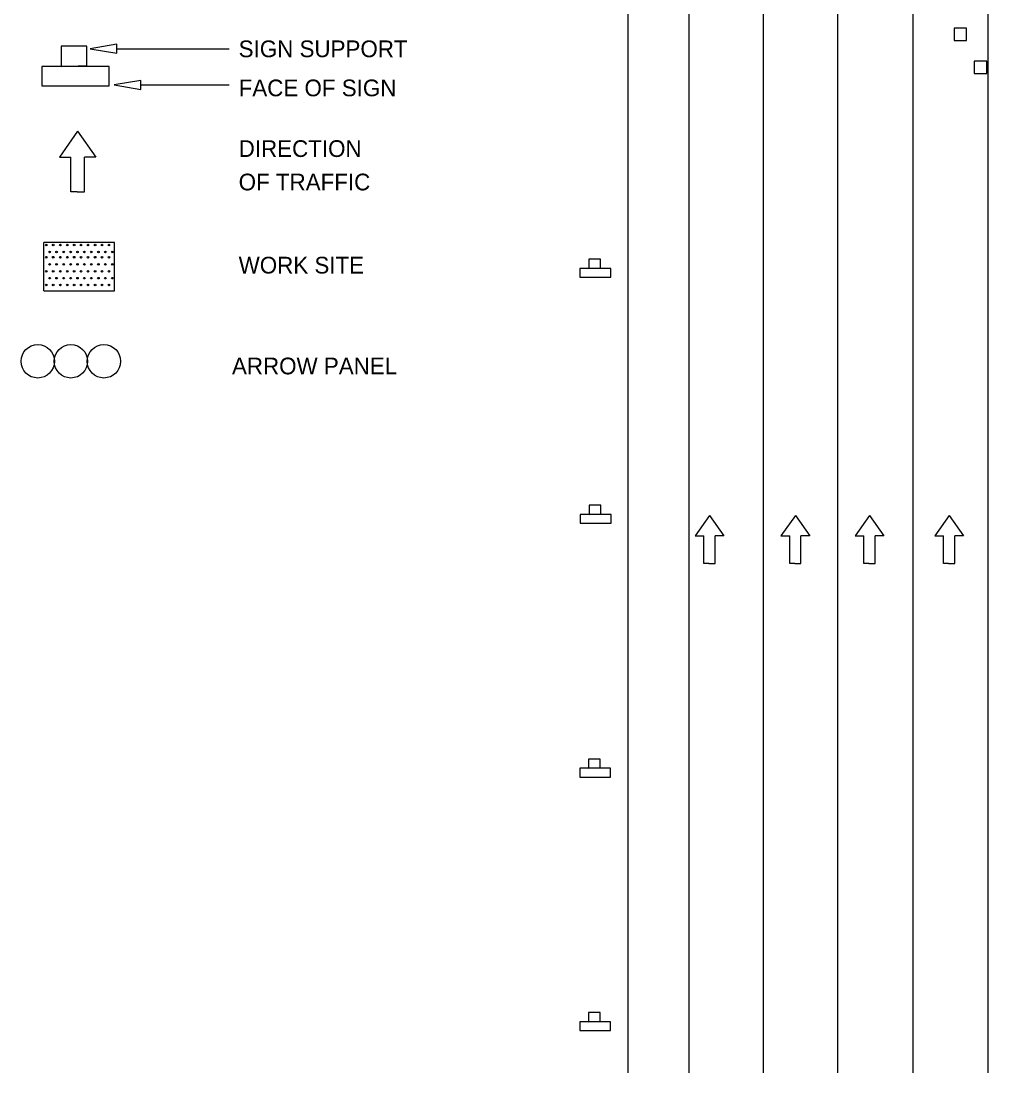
# Model space of a CAD drawing. Extents: x 1531.3 to 1538.6, y 1529.6 to 1539.7.
# Drawn here: x 1531.46 to 1534.931, y 1531.412 to 1535.19 of the extents above; entities that cross this region are included whole.
import ezdxf

# ---------------------------------------------------------------- set-up
doc = ezdxf.new("R2010")
doc.units = 0
for name, color, linetype in [('DETL-DIMS', 7, 'Continuous'), ('DETL-LINE', 7, 'Continuous'), ('DETL-NOTE', 7, 'Continuous'), ('USER-BORD', 7, 'Continuous')]:
    doc.layers.add(name, color=color, linetype=linetype)

# ---------------------------------------------------------------- blocks, each defined once
blk = doc.blocks.new('TD')
at = {"layer": 'USER-BORD'}
for p, q in [((0, 0), (-0.0054, -0.0077)), ((0, 0), (0.0054, -0.0077)), ((-0.0054, -0.0077), (-0.0021, -0.0077)), ((-0.0021, -0.018), (-0.0021, -0.0077)), ((0.0021, -0.018), (0.0021, -0.0077)), ((0.0054, -0.0077), (0.0021, -0.0077)), ((-0.0002, -0.018), (-0.0021, -0.018)), ((-0.0002, -0.018), (0.0002, -0.018)), ((0.0002, -0.018), (0.0021, -0.018))]:
    blk.add_line(p, q, dxfattribs=at)
blk = doc.blocks.new('PANEL0')
at = {"layer": 'USER-BORD'}
for centre in [(0.00309, -0.00012), (0.00928, -0.00012), (0.01546, -0.00012)]:
    blk.add_circle(centre, 0.00312, dxfattribs=at)
blk = doc.blocks.new('DIR4')
at = {"layer": 'USER-BORD'}
for p, q in [((0, 0.0001), (-0.0034, -0.0048)), ((0, 0.0001), (0.0034, -0.0048)), ((-0.0034, -0.0048), (-0.0013, -0.0048)), ((-0.0013, -0.0113), (-0.0013, -0.0048)), ((0.0034, -0.0048), (0.0013, -0.0048)), ((0.0013, -0.0113), (0.0013, -0.0048)), ((-0.0001, -0.0113), (-0.0013, -0.0113)), ((-0.0001, -0.0113), (0.0001, -0.0113)), ((0.0001, -0.0113), (0.0013, -0.0113))]:
    blk.add_line(p, q, dxfattribs=at)
blk = doc.blocks.new('SIGN15')
at = {"layer": 'USER-BORD'}
for points in [[(-0.0013, 0.0018), (0.0011, 0.0019), (0.0011, 0.0037), (-0.0013, 0.0037)], [(-0.0031, 0.0018), (-0.0031, 0), (0.0032, 0), (0.0032, 0.0018)]]:
    blk.add_lwpolyline(points, close=True, dxfattribs=at)

msp = doc.modelspace()

# ---------------------------------------------------------------- linework, layer by layer
at = {"layer": 'DETL-DIMS'}
for p, q in [((1531.8045, 1535.0902), (1532.2068, 1535.0902)), ((1531.89, 1534.9606), (1532.2068, 1534.9606))]:
    msp.add_line(p, q, dxfattribs=at)
for points in [[(1531.8045, 1535.0739), (1531.8045, 1535.1066), (1531.7085, 1535.0902)], [(1531.89, 1534.9443), (1531.89, 1534.976), (1531.794, 1534.9606)]]:
    msp.add_lwpolyline(points, close=True, dxfattribs=at)
at = {"layer": 'DETL-LINE'}
for p, q in [((1533.6384, 1539.3543), (1533.6384, 1531.4117)), ((1533.8574, 1539.3543), (1533.8574, 1531.4117)), ((1534.1244, 1539.3543), (1534.1244, 1531.4117)), ((1534.3913, 1539.3543), (1534.3913, 1531.4117)), ((1534.6611, 1539.3543), (1534.6611, 1531.4117)), ((1534.9308, 1539.3543), (1534.9308, 1531.4117)), ((1531.7955, 1534.3942), (1531.5415, 1534.3942)), ((1531.7955, 1534.3942), (1531.5415, 1534.3942)), ((1531.7955, 1534.3942), (1531.5415, 1534.3942)), ((1531.7955, 1534.3942), (1531.5415, 1534.3942)), ((1531.5415, 1534.2201), (1531.5415, 1534.3941)), ((1531.5416, 1534.2201), (1531.5416, 1534.3941)), ((1531.5501, 1534.3853), (1531.5501, 1534.3853)), ((1531.5509, 1534.3853), (1531.5509, 1534.3853)), ((1531.5629, 1534.3605), (1531.5629, 1534.3605)), ((1531.5629, 1534.3605), (1531.5629, 1534.3605)), ((1531.5757, 1534.3853), (1531.5757, 1534.3853)), ((1531.5757, 1534.3853), (1531.5757, 1534.3853)), ((1531.5877, 1534.3605), (1531.5877, 1534.3605)), ((1531.5877, 1534.3605), (1531.5877, 1534.3605)), ((1531.6005, 1534.3853), (1531.6005, 1534.3853)), ((1531.6013, 1534.3853), (1531.6013, 1534.3853)), ((1531.6133, 1534.3605), (1531.6133, 1534.3605)), ((1531.6133, 1534.3605), (1531.6133, 1534.3605)), ((1531.6253, 1534.3853), (1531.6253, 1534.3853)), ((1531.6261, 1534.3853), (1531.6261, 1534.3853)), ((1531.6381, 1534.3605), (1531.6381, 1534.3605)), ((1531.6381, 1534.3605), (1531.6381, 1534.3605)), ((1531.6501, 1534.3853), (1531.6501, 1534.3853)), ((1531.6509, 1534.3853), (1531.6509, 1534.3853)), ((1531.6629, 1534.3605), (1531.6629, 1534.3605)), ((1531.6629, 1534.3605), (1531.6629, 1534.3605)), ((1531.6757, 1534.3853), (1531.6757, 1534.3853)), ((1531.6757, 1534.3853), (1531.6757, 1534.3853)), ((1531.6877, 1534.3605), (1531.6877, 1534.3605)), ((1531.6877, 1534.3605), (1531.6877, 1534.3605)), ((1531.7005, 1534.3853), (1531.7005, 1534.3853)), ((1531.7005, 1534.3853), (1531.7005, 1534.3853)), ((1531.7125, 1534.3605), (1531.7125, 1534.3605)), ((1531.7125, 1534.3605), (1531.7125, 1534.3605)), ((1531.7253, 1534.3853), (1531.7253, 1534.3853)), ((1531.7261, 1534.3853), (1531.7261, 1534.3853)), ((1531.7381, 1534.3605), (1531.7381, 1534.3605)), ((1531.7381, 1534.3605), (1531.7381, 1534.3605)), ((1531.7501, 1534.3853), (1531.7501, 1534.3853)), ((1531.7509, 1534.3853), (1531.7509, 1534.3853)), ((1531.7629, 1534.3605), (1531.7629, 1534.3605)), ((1531.7629, 1534.3605), (1531.7629, 1534.3605)), ((1531.7757, 1534.3853), (1531.7757, 1534.3853)), ((1531.7757, 1534.3853), (1531.7757, 1534.3853)), ((1531.7877, 1534.3605), (1531.7877, 1534.3605)), ((1531.7877, 1534.3605), (1531.7877, 1534.3605)), ((1531.7955, 1534.2202), (1531.7955, 1534.3942)), ((1531.7955, 1534.2202), (1531.7955, 1534.3942)), ((1531.7955, 1534.2202), (1531.7955, 1534.3942)), ((1531.7955, 1534.2202), (1531.7955, 1534.3942)), ((1531.5501, 1534.3415), (1531.5501, 1534.3415)), ((1531.5509, 1534.3415), (1531.5509, 1534.3415)), ((1531.5757, 1534.3415), (1531.5757, 1534.3415)), ((1531.5757, 1534.3415), (1531.5757, 1534.3415)), ((1531.6005, 1534.3415), (1531.6005, 1534.3415)), ((1531.6013, 1534.3415), (1531.6013, 1534.3415)), ((1531.6253, 1534.3415), (1531.6253, 1534.3415)), ((1531.6261, 1534.3415), (1531.6261, 1534.3415)), ((1531.6501, 1534.3415), (1531.6501, 1534.3415)), ((1531.6509, 1534.3415), (1531.6509, 1534.3415)), ((1531.6757, 1534.3415), (1531.6757, 1534.3415)), ((1531.6757, 1534.3415), (1531.6757, 1534.3415)), ((1531.7005, 1534.3415), (1531.7005, 1534.3415)), ((1531.7005, 1534.3415), (1531.7005, 1534.3415)), ((1531.7253, 1534.3415), (1531.7253, 1534.3415)), ((1531.7261, 1534.3415), (1531.7261, 1534.3415)), ((1531.7501, 1534.3415), (1531.7501, 1534.3415)), ((1531.7509, 1534.3415), (1531.7509, 1534.3415)), ((1531.7757, 1534.3415), (1531.7757, 1534.3415)), ((1531.7757, 1534.3415), (1531.7757, 1534.3415)), ((1531.5501, 1534.2911), (1531.5501, 1534.2911)), ((1531.5509, 1534.2911), (1531.5509, 1534.2911)), ((1531.5629, 1534.3159), (1531.5629, 1534.3159)), ((1531.5757, 1534.2911), (1531.5757, 1534.2911)), ((1531.5757, 1534.2911), (1531.5757, 1534.2911)), ((1531.5877, 1534.3159), (1531.5877, 1534.3159)), ((1531.6005, 1534.2911), (1531.6005, 1534.2911)), ((1531.6013, 1534.2911), (1531.6013, 1534.2911)), ((1531.6133, 1534.3159), (1531.6133, 1534.3159)), ((1531.6253, 1534.2911), (1531.6253, 1534.2911)), ((1531.6261, 1534.2911), (1531.6261, 1534.2911)), ((1531.6381, 1534.3159), (1531.6381, 1534.3159)), ((1531.6501, 1534.2911), (1531.6501, 1534.2911)), ((1531.6509, 1534.2911), (1531.6509, 1534.2911)), ((1531.6629, 1534.3159), (1531.6629, 1534.3159)), ((1531.6757, 1534.2911), (1531.6757, 1534.2911)), ((1531.6757, 1534.2911), (1531.6757, 1534.2911)), ((1531.6877, 1534.3159), (1531.6877, 1534.3159)), ((1531.7005, 1534.2911), (1531.7005, 1534.2911)), ((1531.7005, 1534.2911), (1531.7005, 1534.2911)), ((1531.7125, 1534.3159), (1531.7125, 1534.3159)), ((1531.7253, 1534.2911), (1531.7253, 1534.2911)), ((1531.7261, 1534.2911), (1531.7261, 1534.2911)), ((1531.7381, 1534.3159), (1531.7381, 1534.3159)), ((1531.7501, 1534.2911), (1531.7501, 1534.2911)), ((1531.7509, 1534.2911), (1531.7509, 1534.2911)), ((1531.7629, 1534.3159), (1531.7629, 1534.3159)), ((1531.7757, 1534.2911), (1531.7757, 1534.2911)), ((1531.7757, 1534.2911), (1531.7757, 1534.2911)), ((1531.7877, 1534.3159), (1531.7877, 1534.3159)), ((1531.5629, 1534.2663), (1531.5629, 1534.2663)), ((1531.5629, 1534.2663), (1531.5629, 1534.2663)), ((1531.5877, 1534.2663), (1531.5877, 1534.2663)), ((1531.5877, 1534.2663), (1531.5877, 1534.2663)), ((1531.6133, 1534.2663), (1531.6133, 1534.2663)), ((1531.6133, 1534.2663), (1531.6133, 1534.2663)), ((1531.6381, 1534.2663), (1531.6381, 1534.2663)), ((1531.6381, 1534.2663), (1531.6381, 1534.2663)), ((1531.6629, 1534.2663), (1531.6629, 1534.2663)), ((1531.6629, 1534.2663), (1531.6629, 1534.2663)), ((1531.6877, 1534.2663), (1531.6877, 1534.2663)), ((1531.6877, 1534.2663), (1531.6877, 1534.2663)), ((1531.7125, 1534.2663), (1531.7125, 1534.2663)), ((1531.7125, 1534.2663), (1531.7125, 1534.2663)), ((1531.7381, 1534.2663), (1531.7381, 1534.2663)), ((1531.7381, 1534.2663), (1531.7381, 1534.2663)), ((1531.7629, 1534.2663), (1531.7629, 1534.2663)), ((1531.7629, 1534.2663), (1531.7629, 1534.2663)), ((1531.7877, 1534.2663), (1531.7877, 1534.2663)), ((1531.7877, 1534.2663), (1531.7877, 1534.2663)), ((1531.5415, 1534.2201), (1531.7955, 1534.2201)), ((1531.5501, 1534.2419), (1531.5501, 1534.2419)), ((1531.5509, 1534.2419), (1531.5509, 1534.2419)), ((1531.5757, 1534.2419), (1531.5757, 1534.2419)), ((1531.5757, 1534.2419), (1531.5757, 1534.2419)), ((1531.6005, 1534.2419), (1531.6005, 1534.2419)), ((1531.6013, 1534.2419), (1531.6013, 1534.2419)), ((1531.6253, 1534.2419), (1531.6253, 1534.2419)), ((1531.6261, 1534.2419), (1531.6261, 1534.2419)), ((1531.6501, 1534.2419), (1531.6501, 1534.2419)), ((1531.6509, 1534.2419), (1531.6509, 1534.2419)), ((1531.6757, 1534.2419), (1531.6757, 1534.2419)), ((1531.6757, 1534.2419), (1531.6757, 1534.2419)), ((1531.7005, 1534.2419), (1531.7005, 1534.2419)), ((1531.7005, 1534.2419), (1531.7005, 1534.2419)), ((1531.7253, 1534.2419), (1531.7253, 1534.2419)), ((1531.7261, 1534.2419), (1531.7261, 1534.2419)), ((1531.7501, 1534.2419), (1531.7501, 1534.2419)), ((1531.7509, 1534.2419), (1531.7509, 1534.2419)), ((1531.7757, 1534.2419), (1531.7757, 1534.2419)), ((1531.7757, 1534.2419), (1531.7757, 1534.2419))]:
    msp.add_line(p, q, dxfattribs=at)
for points in [[(1534.8091, 1535.1193), (1534.8539, 1535.1193), (1534.8539, 1535.1641), (1534.8091, 1535.1641)], [(1534.8814, 1535.0007), (1534.9262, 1535.0007), (1534.9262, 1535.0455), (1534.8814, 1535.0455)]]:
    msp.add_lwpolyline(points, close=True, dxfattribs=at)
for points in [[(1534.1244, 1534.9106), (1534.1244, 1534.8543)], [(1534.3913, 1534.9106), (1534.3913, 1534.8543)], [(1534.1244, 1534.8543), (1534.1244, 1534.7981)], [(1534.3913, 1534.8543), (1534.3913, 1534.7981)], [(1534.1244, 1534.4606), (1534.1244, 1534.4043)], [(1534.3913, 1534.4606), (1534.3913, 1534.4043)], [(1534.6611, 1534.4606), (1534.6611, 1534.4043)], [(1534.1244, 1534.4043), (1534.1244, 1534.3481)], [(1534.3913, 1534.4043), (1534.3913, 1534.3481)], [(1534.6611, 1534.4043), (1534.6611, 1534.3481)], [(1534.1244, 1534.0106), (1534.1244, 1533.9543)], [(1534.3913, 1534.0106), (1534.3913, 1533.9543)], [(1534.6611, 1534.0106), (1534.6611, 1533.9543)], [(1534.1244, 1533.9543), (1534.1244, 1533.8981)], [(1534.3913, 1533.9543), (1534.3913, 1533.8981)], [(1534.6611, 1533.9543), (1534.6611, 1533.8981)], [(1534.1244, 1533.5606), (1534.1244, 1533.5043)], [(1534.3913, 1533.5606), (1534.3913, 1533.5043)], [(1534.6611, 1533.5606), (1534.6611, 1533.5043)], [(1534.1244, 1533.5043), (1534.1244, 1533.4481)], [(1534.3913, 1533.5043), (1534.3913, 1533.4481)], [(1534.6611, 1533.5043), (1534.6611, 1533.4481)], [(1534.1244, 1533.1106), (1534.1244, 1533.0543)], [(1534.3913, 1533.1106), (1534.3913, 1533.0543)], [(1534.6611, 1533.1106), (1534.6611, 1533.0543)], [(1534.1244, 1533.0543), (1534.1244, 1532.9981)], [(1534.3913, 1533.0543), (1534.3913, 1532.9981)], [(1534.6611, 1533.0543), (1534.6611, 1532.9981)], [(1534.1244, 1532.6606), (1534.1244, 1532.6043)], [(1534.3913, 1532.6606), (1534.3913, 1532.6043)], [(1534.6611, 1532.6606), (1534.6611, 1532.6043)], [(1534.1244, 1532.6043), (1534.1244, 1532.5481)], [(1534.3913, 1532.6043), (1534.3913, 1532.5481)], [(1534.6611, 1532.6043), (1534.6611, 1532.5481)], [(1534.1244, 1532.2106), (1534.1244, 1532.1543)], [(1534.3913, 1532.2106), (1534.3913, 1532.1543)], [(1534.6611, 1532.2106), (1534.6611, 1532.1543)], [(1534.1244, 1532.1543), (1534.1244, 1532.0981)], [(1534.3913, 1532.1543), (1534.3913, 1532.0981)], [(1534.6611, 1532.1543), (1534.6611, 1532.0981)], [(1534.1244, 1531.7606), (1534.1244, 1531.7043)], [(1534.3913, 1531.7606), (1534.3913, 1531.7043)], [(1534.6611, 1531.7606), (1534.6611, 1531.7043)], [(1534.1244, 1531.7043), (1534.1244, 1531.6481)], [(1534.3913, 1531.7043), (1534.3913, 1531.6481)], [(1534.6611, 1531.7043), (1534.6611, 1531.6481)]]:
    msp.add_lwpolyline(points, dxfattribs=at)
for centre in [(1531.5508, 1534.3852), (1531.5628, 1534.3604), (1531.5756, 1534.3852), (1531.5876, 1534.3604), (1531.6012, 1534.3852), (1531.6132, 1534.3604), (1531.626, 1534.3852), (1531.638, 1534.3604), (1531.6508, 1534.3852), (1531.6628, 1534.3604), (1531.6756, 1534.3852), (1531.6876, 1534.3604), (1531.7004, 1534.3852), (1531.7124, 1534.3604), (1531.726, 1534.3852), (1531.738, 1534.3604), (1531.7508, 1534.3852), (1531.7628, 1534.3604), (1531.7756, 1534.3852), (1531.7876, 1534.3604), (1531.5508, 1534.3414), (1531.5756, 1534.3414), (1531.6012, 1534.3414), (1531.626, 1534.3414), (1531.6508, 1534.3414), (1531.6756, 1534.3414), (1531.7004, 1534.3414), (1531.726, 1534.3414), (1531.7508, 1534.3414), (1531.7756, 1534.3414), (1531.5508, 1534.291), (1531.5628, 1534.3158), (1531.5756, 1534.291), (1531.5876, 1534.3158), (1531.6012, 1534.291), (1531.6132, 1534.3158), (1531.626, 1534.291), (1531.638, 1534.3158), (1531.6508, 1534.291), (1531.6628, 1534.3158), (1531.6756, 1534.291), (1531.6876, 1534.3158), (1531.7004, 1534.291), (1531.7124, 1534.3158), (1531.726, 1534.291), (1531.738, 1534.3158), (1531.7508, 1534.291), (1531.7628, 1534.3158), (1531.7756, 1534.291), (1531.7876, 1534.3158), (1531.5628, 1534.2662), (1531.5876, 1534.2662), (1531.6132, 1534.2662), (1531.638, 1534.2662), (1531.6628, 1534.2662), (1531.6876, 1534.2662), (1531.7124, 1534.2662), (1531.738, 1534.2662), (1531.7628, 1534.2662), (1531.7876, 1534.2662), (1531.5508, 1534.2418), (1531.5756, 1534.2418), (1531.6012, 1534.2418), (1531.626, 1534.2418), (1531.6508, 1534.2418), (1531.6756, 1534.2418), (1531.7004, 1534.2418), (1531.726, 1534.2418), (1531.7508, 1534.2418), (1531.7756, 1534.2418)]:
    msp.add_circle(centre, 0.00291, dxfattribs=at)

# ---------------------------------------------------------------- block references
for name, p, xscale, yscale in [('SIGN15', (1531.6538, 1534.9568), 38.4, 38.4), ('DIR4', (1531.6634, 1534.7926), 19.2, 19.2), ('SIGN15', (1533.5206, 1534.2695), 17.523809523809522, 17.523809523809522), ('PANEL0', (1531.4608, 1533.9698), 19.2, 19.2), ('SIGN15', (1533.5217, 1533.3861), 17.523809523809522, 17.523809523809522), ('TD', (1533.9314, 1533.4141), 9.6, 9.6), ('TD', (1534.2395, 1533.4141), 9.6, 9.6), ('TD', (1534.5054, 1533.4141), 9.6, 9.6), ('TD', (1534.7915, 1533.4141), 9.6, 9.6), ('SIGN15', (1533.5198, 1532.4744), 17.523809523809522, 17.523809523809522), ('SIGN15', (1533.5198, 1531.5637), 17.523809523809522, 17.523809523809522)]:
    msp.add_blockref(name, p, dxfattribs=dict(at, xscale=xscale, yscale=yscale))

# ---------------------------------------------------------------- texts
at = {"layer": 'DETL-NOTE'}
for s, p in [('SIGN SUPPORT', (1532.2413, 1535.0598)), ('FACE OF SIGN', (1532.2413, 1534.9194)), ('DIRECTION', (1532.2413, 1534.7015)), ('OF TRAFFIC', (1532.2413, 1534.5815)), ('WORK SITE', (1532.2413, 1534.2829)), ('ARROW PANEL', (1532.2173, 1533.9208))]:
    msp.add_text(s, height=0.06, dxfattribs=at).set_placement(p)

doc.saveas('drawing.dxf')
